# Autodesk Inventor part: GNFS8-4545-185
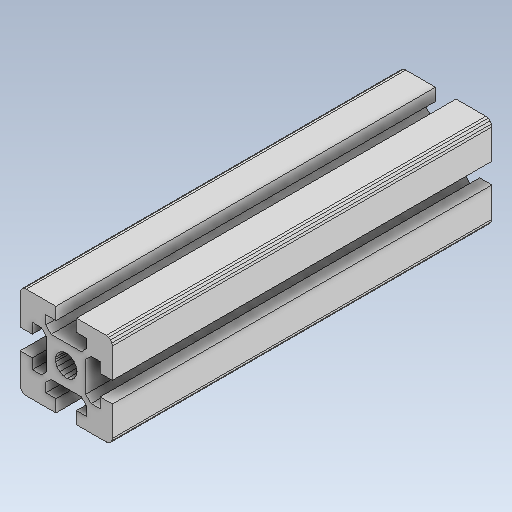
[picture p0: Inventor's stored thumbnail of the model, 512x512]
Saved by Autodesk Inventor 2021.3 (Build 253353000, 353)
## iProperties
Created: 2022-02
Part Number: GNFS8-4545-185
Material: 一般
Document SubType Name: Modeling
Designer: kengo
Density: 1 g/cm^3
Appearance: 既定
Author: kengo
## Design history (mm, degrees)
feature "GNFS8-4545-185"
node "ソリッド1"
